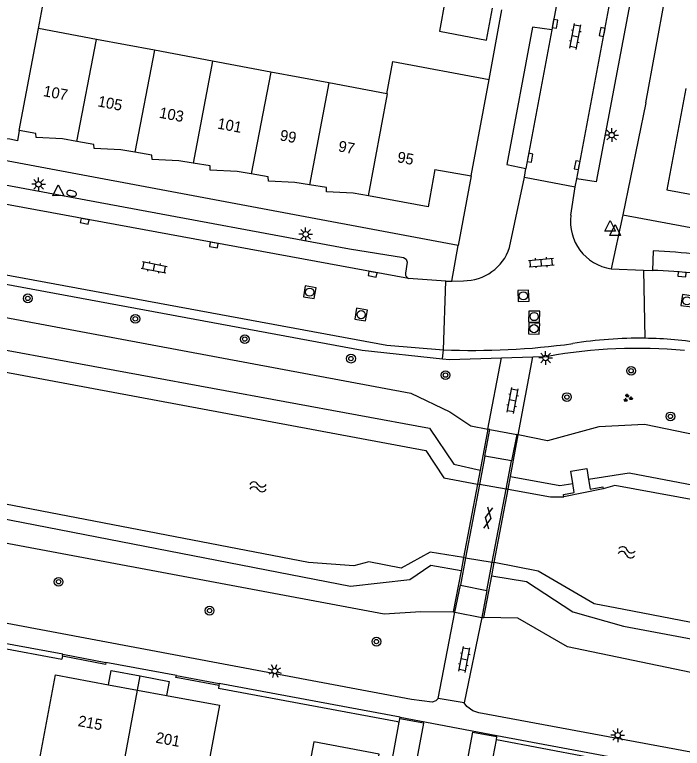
# Model space of a CAD drawing. Extents: x 124000 to 128010, y 398999 to 403000.
# Drawn here: x 126636.3 to 126697.3, y 399560.1 to 399627.2 of the extents above; entities that cross this region are included whole.
import ezdxf

# ---------------------------------------------------------------- set-up
doc = ezdxf.new("R2010")
doc.units = 0
for name, color, linetype in [('gg-afsc-hekwerk', 7, 'Continuous'), ('gg-afsc-muur', 7, 'Continuous'), ('gg-anno-huisnummerreeks BGT', 7, 'Continuous'), ('gg-bbg-gedigitaliseerde bebouwing', 7, 'Continuous'), ('gg-bbg-hoofdgebouw', 7, 'Continuous'), ('gg-bbg-luifel en loopbrug', 7, 'Continuous'), ('gg-bbg-tussenscheiding', 7, 'Continuous'), ('gg-knt-BGT kruinlijn', 7, 'Continuous'), ('gg-knt-verharding', 7, 'Continuous'), ('gg-knt-verharding nz', 7, 'Continuous'), ('gg-kntw-beschoeiing', 7, 'Continuous'), ('gg-kwrk-kunstwerk niveau 01', 7, 'Continuous'), ('gg-kwrk-uitstroombak niveau min 01', 7, 'Continuous'), ('gt-grn-groengrens', 7, 'Continuous'), ('gt-grn-vlakafsluiter', 7, 'Continuous'), ('gt-grn-weggrens', 7, 'Continuous'), ('gt-symb-boom', 7, 'Continuous'), ('gt-symb-brandkraan', 7, 'Continuous'), ('gt-symb-gesloten verharding', 7, 'Continuous'), ('gt-symb-groenvak', 7, 'Continuous'), ('gt-symb-klinker verharding', 7, 'Continuous'), ('gt-symb-kolk', 7, 'Continuous'), ('gt-symb-lichtmast', 7, 'Continuous'), ('gt-symb-rioolschacht', 7, 'Continuous'), ('gt-symb-waterafsluiter', 7, 'Continuous'), ('gt-symb-watersymbool', 7, 'Continuous')]:
    doc.layers.add(name, color=color, linetype=linetype)

# ---------------------------------------------------------------- blocks, each defined once
blk = doc.blocks.new('gt0-KOLK')
at = {"layer": 'gt-symb-kolk'}
blk.add_lwpolyline([(0, 0), (0.375, 0), (0.375, 0.4), (-0.375, 0.4), (-0.375, 0), (0, 0)], dxfattribs=at)
blk = doc.blocks.new('gt0-KL1')
at = {"layer": 'gt-symb-klinker verharding'}
for p, q in [((-1.15, 0.3), (1.15, 0.3)), ((-1, -0.3), (-1, 0.3)), ((-0.5, 0.3), (-0.5, 0.45)), ((0, -0.3), (0, 0.3)), ((0.5, 0.3), (0.5, 0.45)), ((1, -0.3), (1, 0.3)), ((-1.15, -0.3), (1.15, -0.3)), ((-0.5, -0.45), (-0.5, -0.3)), ((0.5, -0.45), (0.5, -0.3))]:
    blk.add_line(p, q, dxfattribs=at)
blk = doc.blocks.new('gt0-LMAST')
at = {"layer": 'gt-symb-lichtmast'}
for p, q in [((-0.182, 0.173), (-0.447, 0.438)), ((-0.005, 0.246), (-0.005, 0.621)), ((0.172, 0.173), (0.437, 0.438)), ((-0.255, -0.004), (-0.63, -0.004)), ((-0.182, -0.181), (-0.447, -0.446)), ((-0.005, -0.254), (-0.005, -0.629)), ((0.437, -0.446), (0.172, -0.181)), ((0.245, -0.004), (0.62, -0.004))]:
    blk.add_line(p, q, dxfattribs=at)
blk.add_circle((-0.005, -0.004), 0.25, dxfattribs=at)
blk = doc.blocks.new('gt0-WAFSL')
at = {"layer": 'gt-symb-waterafsluiter'}
for p, q in [((-0.5, -0.333), (0, 0.667)), ((0, 0.667), (0.5, -0.333)), ((0.5, -0.333), (-0.5, -0.333))]:
    blk.add_line(p, q, dxfattribs=at)
blk = doc.blocks.new('gt0-BOOM')
at = {"layer": 'gt-symb-boom'}
for radius in [0.4, 0.2]:
    blk.add_circle((0, 0), radius, dxfattribs=at)
blk = doc.blocks.new('gt0-RS')
at = {"layer": 'gt-symb-rioolschacht'}
blk.add_lwpolyline([(-0.5, -0.5), (0.5, -0.5), (0.5, 0.5), (-0.5, 0.5)], close=True, dxfattribs=at)
blk.add_circle((0, 0), 0.375, dxfattribs=at)
blk = doc.blocks.new('gt0-GRVAK')
at = {"layer": 'gt-symb-groenvak'}
for p, q in [((-0.11, 0.189), (-0.228, 0.24)), ((-0.182, 0.153), (0.088, 0.153)), ((-0.091, 0.211), (-0.156, 0.322)), ((-0.047, 0.214), (-0.047, 0.393)), ((-0.004, 0.211), (0.061, 0.322)), ((0.015, 0.189), (0.133, 0.24)), ((0.262, -0.052), (0.197, 0.059)), ((0.305, -0.049), (0.305, 0.13)), ((0.349, -0.052), (0.414, 0.059)), ((-0.245, -0.228), (-0.363, -0.177)), ((-0.318, -0.264), (-0.047, -0.264)), ((-0.226, -0.206), (-0.291, -0.095)), ((-0.183, -0.203), (-0.183, -0.024)), ((-0.139, -0.206), (-0.074, -0.095)), ((-0.12, -0.228), (-0.002, -0.177)), ((0.243, -0.074), (0.125, -0.023)), ((0.17, -0.11), (0.441, -0.11)), ((0.368, -0.074), (0.486, -0.023))]:
    blk.add_line(p, q, dxfattribs=at)
blk = doc.blocks.new('gt0-WA')
at = {"layer": 'gt-symb-watersymbool'}
for centre, start, end in [((-0.323, 0.022), 28.07249, 151.92751), ((0.427, 0.422), 208.07248, 331.92751), ((-0.323, -0.428), 28.07249, 151.92751), ((0.427, -0.028), 208.07248, 331.92751)]:
    blk.add_arc(centre, 0.425, start, end, dxfattribs=at)
blk = doc.blocks.new('gt0-GESVH1')
at = {"layer": 'gt-symb-gesloten verharding'}
for p, q in [((-0.992, -0.261), (0.008, 0.239)), ((0.008, -0.261), (-0.992, 0.239)), ((0.008, 0.239), (1.008, -0.261)), ((1.008, 0.239), (0.008, -0.261))]:
    blk.add_line(p, q, dxfattribs=at)
blk = doc.blocks.new('gt0-BR')
at = {"layer": 'gt-symb-brandkraan'}
for centre, radius, start, end in [((-0.244, 0), 0.206, 107.56694, 252.43307), ((0.599, -2.664), 3, 106.89205, 107.56694), ((0, -0.691), 0.938, 73.10799, 106.89205), ((-0.599, -2.664), 3, 72.43309, 73.10799), ((0.244, 0), 0.206, 287.56695, 72.43309), ((0.599, 2.664), 3, 252.43307, 253.10797), ((0, 0.691), 0.938, 253.10797, 286.89206), ((-0.599, 2.664), 3, 286.89206, 287.56695)]:
    blk.add_arc(centre, radius, start, end, dxfattribs=at)

msp = doc.modelspace()

# ---------------------------------------------------------------- linework, layer by layer
at = {"layer": 'gg-afsc-hekwerk'}
for p, q in [((126624.243, 399571.352), (126640.607, 399568.275)), ((126671.314, 399562.54), (126654.902, 399565.591)), ((126696.661, 399557.827), (126680.321, 399560.897))]:
    msp.add_line(p, q, dxfattribs=at)
at = {"layer": 'gg-afsc-muur'}
for p, q in [((126693.945, 399619.15), (126695.841, 399629.445)), ((126679.651, 399621.275), (126680.797, 399627.637)), ((126640.656, 399568.544), (126640.692, 399568.73)), ((126640.692, 399568.73), (126644.61, 399567.99)), ((126651.067, 399566.791), (126654.989, 399566.064)), ((126654.989, 399566.064), (126654.953, 399565.87))]:
    msp.add_line(p, q, dxfattribs=at)
for points in [[(126644.61, 399567.99), (126644.575, 399567.806), (126640.656, 399568.544)], [(126654.953, 399565.87), (126651.03, 399566.595), (126651.067, 399566.791)]]:
    msp.add_lwpolyline(points, dxfattribs=at)
at = {"layer": 'gg-bbg-gedigitaliseerde bebouwing'}
for p, q in [((126643.765, 399624.941), (126638.458, 399625.934)), ((126649.073, 399623.947), (126643.765, 399624.941)), ((126654.38, 399622.954), (126649.073, 399623.947)), ((126659.689, 399621.96), (126654.38, 399622.954)), ((126664.997, 399620.966), (126659.689, 399621.96)), ((126670.282, 399619.977), (126664.997, 399620.966))]:
    msp.add_line(p, q, dxfattribs=at)
msp.add_lwpolyline([(126638.458, 399625.934), (126639.01, 399628.883), (126633.702, 399629.877), (126633.15, 399626.928)], dxfattribs=at)
at = {"layer": 'gg-bbg-hoofdgebouw'}
for p, q in [((126678.002, 399612.468), (126679.651, 399621.275)), ((126674.686, 399613.046), (126678.002, 399612.468)), ((126644.87, 399565.951), (126647.509, 399565.46)), ((126647.509, 399565.46), (126650.148, 399564.969))]:
    msp.add_line(p, q, dxfattribs=at)
for points in [[(126670.282, 399619.977), (126670.833, 399622.917), (126679.651, 399621.275)], [(126697.623, 399620.459), (126695.874, 399611.176), (126701.333, 399610.178)], [(126636.708, 399616.608), (126636.547, 399615.666), (126635.838, 399615.819), (126632.9, 399616.001), (126632.964, 399617.325)], [(126641.981, 399615.617), (126640.671, 399615.845), (126638.248, 399615.959), (126638.222, 399616.348), (126636.708, 399616.608)], [(126647.284, 399614.628), (126645.986, 399614.846), (126643.544, 399614.968), (126643.529, 399615.347), (126641.981, 399615.617)], [(126652.609, 399613.638), (126651.288, 399613.853), (126648.855, 399613.972), (126648.833, 399614.368), (126647.284, 399614.628)], [(126657.908, 399612.648), (126656.619, 399612.867), (126654.166, 399612.983), (126654.159, 399613.386), (126652.609, 399613.638)], [(126663.231, 399611.635), (126661.887, 399611.845), (126659.489, 399611.98), (126659.456, 399612.386), (126657.908, 399612.648)], [(126674.686, 399613.046), (126674.061, 399609.639), (126668.621, 399610.636)], [(126668.621, 399610.636), (126667.228, 399610.891), (126664.787, 399610.997), (126664.782, 399611.392), (126663.231, 399611.635)], [(126638.553, 399559.051), (126640.007, 399566.857), (126644.87, 399565.951)], [(126650.148, 399564.969), (126655.01, 399564.063), (126653.556, 399556.257)]]:
    msp.add_lwpolyline(points, dxfattribs=at)
at = {"layer": 'gg-bbg-luifel en loopbrug'}
msp.add_line((126647.509, 399565.46), (126647.755, 399566.749), dxfattribs=at)
for points in [[(126675.636, 399628.583), (126675.094, 399625.695), (126679.408, 399624.885), (126679.954, 399627.792)], [(126644.87, 399565.951), (126645.119, 399567.253), (126647.755, 399566.749)], [(126647.755, 399566.749), (126650.392, 399566.244), (126650.148, 399564.969)], [(126669.014, 399556.569), (126669.592, 399559.607), (126663.61, 399560.718), (126663.046, 399557.678)]]:
    msp.add_lwpolyline(points, dxfattribs=at)
at = {"layer": 'gg-bbg-tussenscheiding'}
for p, q in [((126636.708, 399616.608), (126638.458, 399625.934)), ((126641.981, 399615.617), (126643.765, 399624.941)), ((126649.073, 399623.947), (126647.284, 399614.628)), ((126654.38, 399622.954), (126652.609, 399613.638)), ((126659.689, 399621.96), (126657.908, 399612.648)), ((126664.997, 399620.966), (126663.231, 399611.635)), ((126646.054, 399557.654), (126647.509, 399565.46))]:
    msp.add_line(p, q, dxfattribs=at)
msp.add_lwpolyline([(126668.621, 399610.636), (126670.343, 399619.966), (126670.282, 399619.977)], dxfattribs=at)
at = {"layer": 'gg-knt-BGT kruinlijn'}
for points in [[(126531.953, 399618.878), (126672.477, 399592.587), (126676.055, 399590.909), (126677.969, 399589.606), (126679.53, 399589.318)], [(126532.02, 399598.31), (126670.063, 399572.435), (126673.392, 399572.629), (126676.357, 399572.6)], [(127000, 399532.278), (126705.207, 399587.393), (126693.827, 399589.723), (126689.664, 399589.521), (126684.973, 399588.254), (126682.307, 399588.784)], [(126787.178, 399550.094), (126703.342, 399565.974), (126686.788, 399569.405), (126682.263, 399572.046), (126679.171, 399572.084)]]:
    msp.add_lwpolyline(points, dxfattribs=at)
at = {"layer": 'gg-knt-verharding'}
for p, q in [((126687.344, 399636.441), (126685.356, 399625.831)), ((126693.945, 399619.15), (126691.87, 399608.892)), ((126676.824, 399606.086), (126614.774, 399617.734)), ((126682.867, 399612.351), (126683.001, 399613.134)), ((126678.002, 399612.468), (126676.824, 399606.086)), ((126682.867, 399612.351), (126687.506, 399611.458)), ((126687.506, 399611.458), (126687.668, 399612.19)), ((126691.87, 399608.892), (126746.72, 399598.625)), ((126694.64, 399605.601), (126694.556, 399603.819)), ((126693.761, 399603.845), (126694.556, 399603.819)), ((126693.761, 399603.845), (126693.87, 399597.62)), ((126675.69, 399602.84), (126672.288, 399603.073)), ((126675.464, 399596.561), (126675.69, 399602.84)), ((126679.53, 399589.318), (126680.757, 399595.83)), ((126680.757, 399595.83), (126683.647, 399595.922)), ((126682.307, 399588.784), (126683.647, 399595.922)), ((126683.647, 399595.922), (126685.015, 399595.966)), ((126674.982, 399564.692), (126676.523, 399572.585)), ((126640.692, 399568.73), (126624.326, 399571.792)), ((126678.985, 399572.099), (126677.375, 399564.289)), ((126651.067, 399566.791), (126644.61, 399567.99)), ((126671.517, 399562.989), (126654.989, 399566.064)), ((126677.375, 399564.289), (126674.982, 399564.692)), ((126671.429, 399562.519), (126671.49, 399562.843)), ((126671.49, 399562.843), (126671.517, 399562.989)), ((126671.517, 399562.989), (126680.347, 399561.317)), ((126785.932, 399543.354), (126678.7, 399563.39)), ((126667.961, 399544.12), (126671.429, 399562.519)), ((126680.27, 399560.906), (126676.804, 399542.508)), ((126680.329, 399561.22), (126680.27, 399560.906)), ((126680.347, 399561.317), (126680.329, 399561.22)), ((126680.347, 399561.317), (126696.737, 399558.253))]:
    msp.add_line(p, q, dxfattribs=at)
for points in [[(126690.949, 399629.743), (126692.7, 399629.35), (126689.419, 399611.911), (126687.668, 399612.19)], [(126685.356, 399625.831), (126683.611, 399626.072), (126681.257, 399613.502), (126683.001, 399613.134)], [(126523.93, 399623.432), (126621.666, 399605.118), (126668.041, 399596.535), (126675.385, 399595.747)], [(126614.371, 399615.586), (126622.935, 399613.976), (126666.874, 399605.799), (126671.806, 399605.016), (126672.047, 399604.859), (126672.143, 399604.588), (126672.004, 399603.557)], [(126627.558, 399604.891), (126670.291, 399596.993), (126675.464, 399596.561)], [(126675.385, 399595.747), (126676.022, 399595.679), (126680.757, 399595.83)], [(126674.982, 399564.692), (126674.776, 399564.464), (126674.441, 399564.356), (126672.562, 399564.589), (126511.618, 399594.854)], [(126678.7, 399563.39), (126678.145, 399563.569), (126677.59, 399563.963), (126677.375, 399564.289)], [(126661.984, 399500), (126673.681, 399562.447), (126671.49, 399562.843)], [(126666.585, 399500), (126678.145, 399561.607), (126680.329, 399561.22)]]:
    msp.add_lwpolyline(points, dxfattribs=at)
for centre, radius, start, end in [((126692.084, 399547.243), 58.414, 79.51729, 87.49235), ((126672.399, 399603.464), 0.406, 166.70427, 254.10258), ((126693.29, 399561.023), 36.602, 80.57981, 89.09243), ((126693.19, 399550.54), 46.156, 84.6688, 100.20137)]:
    msp.add_arc(centre, radius, start, end, dxfattribs=at)
at = {"layer": 'gg-knt-verharding nz'}
for p, q in [((126687.668, 399612.19), (126690.949, 399629.743)), ((126685.356, 399625.831), (126683.001, 399613.134)), ((126681.517, 399605.907), (126682.867, 399612.351)), ((126672.288, 399603.073), (126628.759, 399611.087)), ((126687.109, 399608.876), (126687.506, 399611.458)), ((126690.786, 399603.966), (126693.761, 399603.845)), ((126675.69, 399602.84), (126676.227, 399602.851)), ((126676.227, 399602.851), (126677.286, 399602.872))]:
    msp.add_line(p, q, dxfattribs=at)
for centre, radius, start, end in [((126691.438, 399608.286), 4.369, 172.2387, 261.4189), ((126677.287, 399607.337), 4.465, 269.98122, 341.32439), ((126693.266, 399558.203), 45.634, 78.46777, 88.38), ((126693.289, 399560.969), 36.655, 89.09225, 99.44199), ((126678.125, 399664.45), 67.941, 267.75554, 277.74087)]:
    msp.add_arc(centre, radius, start, end, dxfattribs=at)
at = {"layer": 'gg-kntw-beschoeiing'}
for p, q in [((126678.767, 399584.242), (126678.573, 399584.274)), ((126681.197, 399583.839), (126678.767, 399584.242)), ((126681.373, 399583.81), (126681.197, 399583.839)), ((126677.301, 399577.574), (126677.493, 399577.542)), ((126677.493, 399577.542), (126679.921, 399577.142)), ((126679.921, 399577.142), (126680.115, 399577.11)), ((126740.77, 399563.378), (126691.948, 399572.811))]:
    msp.add_line(p, q, dxfattribs=at)
for points in [[(126571.793, 399606.416), (126673.852, 399587.357), (126675.506, 399584.867), (126678.573, 399584.274)], [(126677.301, 399577.574), (126674.267, 399578.078), (126671.617, 399576.614), (126668.643, 399577.173), (126667.27, 399576.822), (126663.149, 399577.117), (126603.613, 399588.583)], [(126681.373, 399583.81), (126685.248, 399583.12), (126686.465, 399583.138)], [(126700.597, 399582.427), (126691.116, 399584.151), (126690.055, 399583.851)], [(126691.948, 399572.811), (126689.225, 399573.337), (126684.108, 399576.342), (126680.115, 399577.11)]]:
    msp.add_lwpolyline(points, dxfattribs=at)
at = {"layer": 'gg-kwrk-kunstwerk niveau 01'}
for p, q in [((126679.53, 399589.318), (126678.815, 399585.549)), ((126679.264, 399586.854), (126679.691, 399589.292)), ((126679.691, 399589.292), (126679.53, 399589.318)), ((126679.691, 399589.292), (126682.158, 399588.826)), ((126681.594, 399584.988), (126682.307, 399588.784)), ((126682.158, 399588.826), (126681.685, 399586.404)), ((126682.307, 399588.784), (126682.158, 399588.826)), ((126679.264, 399586.854), (126678.767, 399584.242)), ((126681.685, 399586.404), (126679.264, 399586.854)), ((126681.197, 399583.839), (126681.685, 399586.404)), ((126678.815, 399585.549), (126678.573, 399584.274)), ((126681.373, 399583.81), (126681.594, 399584.988)), ((126678.573, 399584.274), (126677.301, 399577.574)), ((126678.767, 399584.242), (126677.493, 399577.542)), ((126679.921, 399577.142), (126681.197, 399583.839)), ((126680.115, 399577.11), (126681.373, 399583.81)), ((126677.493, 399577.542), (126677.018, 399575.046)), ((126677.301, 399577.574), (126677.073, 399576.371)), ((126679.428, 399574.552), (126679.921, 399577.142)), ((126679.888, 399575.899), (126680.115, 399577.11)), ((126677.073, 399576.371), (126676.357, 399572.6)), ((126679.171, 399572.084), (126679.888, 399575.899)), ((126676.523, 399572.585), (126677.018, 399575.046)), ((126677.018, 399575.046), (126679.428, 399574.552)), ((126679.428, 399574.552), (126678.985, 399572.099)), ((126676.357, 399572.6), (126676.523, 399572.585)), ((126676.523, 399572.585), (126678.985, 399572.099)), ((126678.985, 399572.099), (126679.171, 399572.084))]:
    msp.add_line(p, q, dxfattribs=at)
at = {"layer": 'gg-kwrk-uitstroombak niveau min 01'}
msp.add_line((126690.055, 399583.851), (126686.465, 399583.138), dxfattribs=at)
for points in [[(126687.283, 399584.357), (126687.122, 399585.483), (126688.581, 399585.723), (126688.731, 399584.708)], [(126686.465, 399583.138), (126686.429, 399583.326), (126687.403, 399583.515), (126687.283, 399584.357)], [(126688.731, 399584.708), (126688.861, 399583.823), (126690.024, 399584.048), (126690.055, 399583.851)]]:
    msp.add_lwpolyline(points, dxfattribs=at)
at = {"layer": 'gt-grn-groengrens'}
for p, q in [((126640.656, 399568.544), (126640.607, 399568.275)), ((126654.953, 399565.87), (126654.902, 399565.591)), ((126671.314, 399562.54), (126671.429, 399562.519))]:
    msp.add_line(p, q, dxfattribs=at)
for points in [[(126525.228, 399611.902), (126526.331, 399614.464), (126528.748, 399616.222), (126674.207, 399589.404), (126676.404, 399586.107), (126678.815, 399585.549)], [(126677.073, 399576.371), (126674.308, 399576.845), (126672.398, 399575.523), (126666.963, 399574.935), (126528.678, 399601.847), (126526.903, 399603.281), (126525.833, 399605.007), (126525.25, 399606.709), (126524.973, 399607.901)], [(126681.594, 399584.988), (126686.093, 399584.167), (126687.283, 399584.357)], [(127031.407, 399516.954), (127031.756, 399518.92), (127029.879, 399522.161), (127009.635, 399525.925), (127000, 399527.778), (126870.175, 399551.993), (126857.55, 399554.628), (126778.853, 399568.809), (126692.438, 399585.276), (126688.731, 399584.708)], [(126679.888, 399575.899), (126683.061, 399575.383), (126687.279, 399572.619), (126691.934, 399571.31), (126814.728, 399548.258), (126867.774, 399538.33), (127022.231, 399507.612), (127025.36, 399507.675), (127027.276, 399508.355), (127030.476, 399511.716), (127030.741, 399513.207)]]:
    msp.add_lwpolyline(points, dxfattribs=at)
at = {"layer": 'gt-grn-vlakafsluiter'}
msp.add_line((126680.321, 399560.897), (126680.27, 399560.906), dxfattribs=at)
at = {"layer": 'gt-grn-weggrens'}
for p, q in [((126691.87, 399608.892), (126690.786, 399603.966)), ((126676.227, 399602.851), (126676.824, 399606.086)), ((126675.385, 399595.747), (126675.464, 399596.561))]:
    msp.add_line(p, q, dxfattribs=at)

# ---------------------------------------------------------------- block references
at = {"layer": 'gt-symb-boom'}
for p in [(126637.491, 399601.268), (126647.314, 399599.397), (126657.316, 399597.544), (126667.019, 399595.758), (126692.611, 399594.647), (126675.655, 399594.249), (126686.752, 399592.245), (126696.203, 399590.475), (126640.305, 399575.358), (126654.101, 399572.72), (126669.341, 399569.886)]:
    msp.add_blockref('gt0-BOOM', p, dxfattribs=at)
at = {"layer": 'gt-symb-brandkraan', "rotation": 168.1732960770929}
msp.add_blockref('gt0-BR', (126641.497, 399610.862), dxfattribs=at)
at = {"layer": 'gt-symb-gesloten verharding', "rotation": 79.4542656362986}
msp.add_blockref('gt0-GESVH1', (126679.532, 399581.187), dxfattribs=at)
at = {"layer": 'gt-symb-groenvak'}
msp.add_blockref('gt0-GRVAK', (126692.312, 399592.154), dxfattribs=at)
at = {"layer": 'gt-symb-klinker verharding'}
for p, rotation in [((126687.527, 399625.213), 79.28535610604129), ((126684.408, 399604.537), 4.644721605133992), ((126649.041, 399604.115), -10.71464389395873), ((126681.799, 399591.927), 79.21838326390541), ((126677.381, 399568.261), 79.21838326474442)]:
    msp.add_blockref('gt0-KL1', p, dxfattribs=dict(at, rotation=rotation))
at = {"layer": 'gt-symb-kolk'}
for p, rotation in [((126685.468, 399626.4), -100.60205829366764), ((126690.172, 399625.579), 79.3416384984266), ((126683.186, 399614.159), -100.54573436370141), ((126687.882, 399613.415), 80.09492079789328), ((126642.724, 399608.515), 169.56697526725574), ((126654.526, 399606.342), 169.5669752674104), ((126669.032, 399603.67), 169.5669752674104), ((126697.282, 399603.66), 174.95083353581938)]:
    msp.add_blockref('gt0-KOLK', p, dxfattribs=dict(at, rotation=rotation))
at = {"layer": 'gt-symb-lichtmast'}
for p in [(126690.848, 399616.195), (126638.474, 399611.701), (126662.883, 399607.129), (126684.802, 399595.823), (126691.402, 399561.331)]:
    msp.add_blockref('gt0-LMAST', p, dxfattribs=at)
at = {"layer": 'gt-symb-lichtmast', "rotation": -62.615029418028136}
msp.add_blockref('gt0-LMAST', (126660.065, 399567.195), dxfattribs=at)
at = {"layer": 'gt-symb-rioolschacht'}
for p, rotation in [((126663.248, 399601.831), -9.500010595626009), ((126682.774, 399601.497), 92.80805306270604), ((126697.725, 399601.044), 82.12907949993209), ((126667.946, 399599.782), -9.792146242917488), ((126683.759, 399599.604), -0.802088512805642), ((126683.746, 399598.502), 88.05074587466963)]:
    msp.add_blockref('gt0-RS', p, dxfattribs=dict(at, rotation=rotation))
at = {"layer": 'gt-symb-waterafsluiter', "rotation": 0.4583564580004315}
msp.add_blockref('gt0-WAFSL', (126640.281, 399610.992), dxfattribs=at)
at = {"layer": 'gt-symb-waterafsluiter'}
for p in [(126690.699, 399607.732), (126691.158, 399607.345)]:
    msp.add_blockref('gt0-WAFSL', p, dxfattribs=at)
at = {"layer": 'gt-symb-watersymbool'}
msp.add_blockref('gt0-WA', (126658.468, 399584.04), dxfattribs=at)
at = {"layer": 'gt-symb-watersymbool', "rotation": -8.746162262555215}
msp.add_blockref('gt0-WA', (126692.152, 399578.071), dxfattribs=at)

# ---------------------------------------------------------------- texts
at = {"layer": 'gg-anno-huisnummerreeks BGT'}
for s, rotation, p in [('107', 349.4, (126638.845, 399619.767)), ('105', 349.2, (126643.827, 399618.827)), ('103', 349.5, (126649.441, 399617.786)), ('101', 349.4, (126654.755, 399616.798)), ('99', 349.2, (126660.461, 399615.726)), ('97', 349.5, (126665.8, 399614.719)), ('95', 349.6, (126671.19, 399613.723)), ('215', 349.5, (126642.018, 399562.177)), ('201', 349.5, (126649.121, 399560.66))]:
    msp.add_text(s, height=1, rotation=rotation, dxfattribs=at).set_placement(p)

doc.saveas('drawing.dxf')
